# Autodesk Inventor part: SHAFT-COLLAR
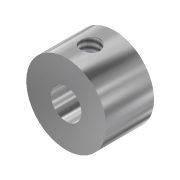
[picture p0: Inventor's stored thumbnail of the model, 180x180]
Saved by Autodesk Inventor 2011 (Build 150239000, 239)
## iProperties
Created: 2008-03
Part Number: SHAFT-COLLAR
Document SubType Name: Modeling
Density: 1 g/cm^3
Mass: 0.517333 g
Surface Area: 4.95075 cm^2
Volume: 0.517333 cm^3
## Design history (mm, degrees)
sketch "Sketch1"
  geometry: C1 r 5.499 at (-7.091, -3.091)
  constraints: 1 centre point
  dimensions: "d0" = 10.9982 diameter of C1
extrude "Extrusion1" new body sketch "Sketch1" distance "d1" = 6.604; taper "d2" = 0 deg
sketch "Sketch2"
  geometry: C1 r 5.499 at (0, 0) reference
hole "Hole1" sketch "Sketch2" at (0, 0) diameter "d3" = 4.191; stored, may be unused: countersink angle "d7" = 82 deg, drill point angle "d9" = 118 deg; dims "d4" = 12.7, "d5" = 9.525, "d6" = 6.35, "d8" = 19.05
workplane "Work Plane1"
sketch "Sketch3"
  geometry: L1 (-5.499, 0)-(5.499, 0) reference; L2 (-5.499, 0)-(-5.499, -6.604) reference; 3 further points
  constraints: 2 midpoint, 1 horizontal alignment, 1 vertical alignment
hole "Hole2" sketch "Sketch3" at (0, -3.302) diameter "d10" = 2.6416; stored, may be unused: countersink angle "d14" = 82 deg, drill point angle "d16" = 118 deg; dims "d11" = 12.7, "d12" = 9.525, "d13" = 6.35, "d15" = 19.05
body "Solid1"
node "Projected Loop1"
